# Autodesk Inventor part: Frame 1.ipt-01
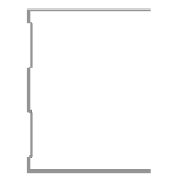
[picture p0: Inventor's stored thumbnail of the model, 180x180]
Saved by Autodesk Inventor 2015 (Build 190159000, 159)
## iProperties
Created: 2015-04
Part Number: Frame 1.ipt-01
Material: Aluminum 6061
Document SubType Name: Modeling
Standard: Unnamed
Designer: suporte
Language: en-US
Size Designation: (Unnamed 1)
Categories: <MemberInstance><Categories><Category DisplayName="Structural Shapes" InternalName="089c4875-fa83-4c05-b084-43b9cc11f5ed" Mnemonic="GRDR"><CategoryParameter Dis
Density: 2.7 g/cm^3
Appearance: Aluminum - Flat
IsCustomPart: 1
_CCFamilyMember: 1
_CCFamilyDisplayName: Frame 1
_FrameMemberDoc: Frame Member File
_Version: 15.0.0
_GetPNFromCC: 1
Author: suporte
G_L: 742,325 mm
G_W: 70,000 mm
G_H: 75,000 mm
+9BC56BD3-3601-4756-9CD3-DFE412EE9504+CUTDETAIL1: Miter 67,51 deg
+371032C4-853D-4D1C-9F66-73CC0C0069CB+CUTDETAIL2: Cut
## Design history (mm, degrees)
node "Start Plane"
node "End Plane"
sketch "Sketch"
  geometry: L1 (34.6, 37.5)-(34.6, 36.7); L2 (34.6, 36.7)-(-34.6, 36.7); L3 (-34.6, -36.7)-(34.6, -36.7); L4 (34.6, -36.7)-(34.6, -37.5); L5 (34.6, -37.5)-(-35.4, -37.5); L6 (-35.4, 37.5)-(34.6, 37.5); L7 (-34.6, 36.7)-(-34.6, 31.7); L8 (-34.6, 31.7)-(-33.4, 30.5); L9 (-33.4, 30.5)-(-33.4, 10.746); L10 (-33.4, 10.746)-(-34.6, 9.546); L11 (-34.6, 9.546)-(-34.6, -9.546); L12 (-34.6, -9.546)-(-33.4, -10.746); L13 (-33.4, -10.746)-(-33.4, -30.5); L14 (-33.4, -30.5)-(-34.6, -31.7); L15 (-34.6, -31.7)-(-34.6, -36.7); L16 (-35.4, -37.5)-(-35.4, -31.369); L17 (-35.4, -31.369)-(-34.2, -30.169); L18 (-34.2, -30.169)-(-34.2, -11.077); L19 (-34.2, -11.077)-(-35.4, -9.877); L20 (-35.4, -9.877)-(-35.4, 9.877); L21 (-35.4, 9.877)-(-34.2, 11.077); L22 (-34.2, 11.077)-(-34.2, 30.169); L23 (-34.2, 30.169)-(-35.4, 31.369); L24 (-35.4, 31.369)-(-35.4, 37.5); L25 (-35.4, 0)-(30.37, 0); 3 further points
  constraints: 50 end point, 10 point on line, 9 parallel, 5 perpendicular, 4 equal length, 3 midpoint, 3 vertical, 2 vertical alignment, 1 collinear, 1 horizontal, 1 horizontal alignment
  dimensions: "d3" = 0.8 distance of L1.start L1.end; "d5" = 75 distance between parallel lines of L5 L6; "d6" = 0.8 distance between parallel lines of L24 L7; "d7" = 0.8 distance between parallel lines of L8 L23; "d8" = 0.8 distance between parallel lines of L22 L9; "d9" = 0.8 distance between parallel lines of L17 L14; "d10" = 0.8 distance between parallel lines of L13 L18; "d11" = 0.8 distance between parallel lines of L12 L19; "d12" = 0.8 distance between parallel lines of L21 L10; "d13" = 5 distance of L2.end L7.end; "d15" = 135 deg angle of L9 L8; "d16" = 2 distance between parallel lines of L24 L9; "d17" = 70 distance of L6.start L1.start
extrude "Body" join sketch "Sketch" stored distance "d24" = 0.13; taper "d25" = 0 deg
node "Driven Length"
  sketch "Sketch8"
    geometry: L1 (0, 0)-(10, 0) reference
    constraints: 2 end point, 1 horizontal
  workplane "Work Plane6"
  sketch "Sketch9"
    geometry: L1 (-2, 12.5)-(12, 12.5) reference; L2 (-2, 754.825)-(12, 754.825) reference
    dimensions: "d27" = 742.32488 distance between parallel lines of L1 L2 (derived)
workplane "Work Plane7"
split "Split1"
workplane "Work Plane8"
split "Split2"
body "Solid1"
other parameters: "tamanho" = 718.59902, "G_OFFSET_START" = -12.5 [user parameter; used in 1 equation term], "G_OFFSET_END" = 36.22585 [user parameter; used in 1 equation term], "d22" = 12.5 (= -G_OFFSET_START), "d23" = 754.82488 (= tamanho + G_OFFSET_END), "G_L" = 742.32488 (= d27) [user parameter], "d32" = 90 deg
